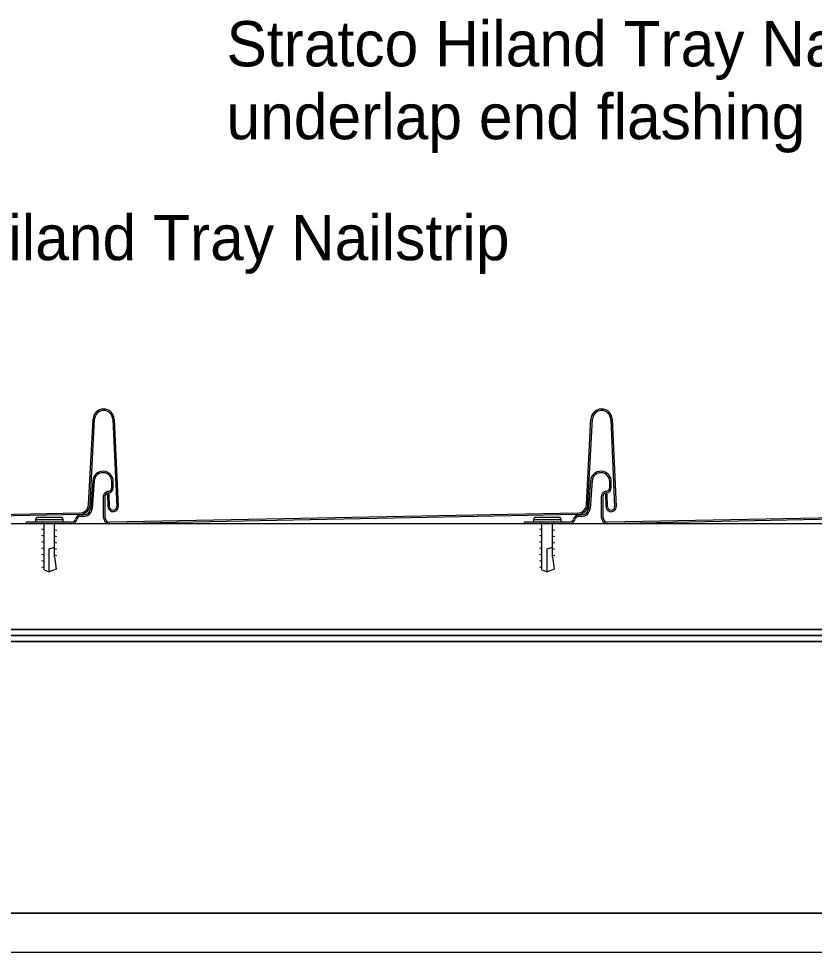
# Model space of a CAD drawing. Extents: x -2.36 to 6.66, y -3.72 to 4.13.
# Drawn here: x 4.3584 to 4.622, y -3.277 to -2.9677 of the extents above; entities that cross this region are included whole.
import ezdxf

# ---------------------------------------------------------------- set-up
doc = ezdxf.new("R2010")
doc.units = 0
for name, color, linetype in [('A-____-____-IDEN', 7, 'Continuous'), ('A-DETL-____-MEDM', 7, 'Continuous'), ('A-DETL-GENF-OTLN', 7, 'Continuous'), ('A-WALL-____-MCUT', 7, 'Continuous'), ('A-WALL-____-PATT', 7, 'Continuous'), ('A-WALL-FNSH-MCUT', 7, 'Continuous')]:
    doc.layers.add(name, color=color, linetype=linetype)

# ---------------------------------------------------------------- blocks, each defined once
blk = doc.blocks.new('Detail Repeating_Stratco_Hiland_Tray_Nailstrip - Rib Height 38mm_165mm Coverage-Detail Flashings - Hiland Nailstrip End Caps')
at = {"layer": 'A-DETL-____-MEDM'}
for p, q in [((0.17571069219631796, 7.14861503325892e-16), (0.1905651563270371, 7.14861503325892e-16)), ((0.1905651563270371, 7.14861503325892e-16), (0.1905651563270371, -0.0004999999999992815)), ((0.3407106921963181, 1.4974022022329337e-15), (0.35556515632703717, 1.4974022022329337e-15)), ((0.35556515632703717, 1.4974022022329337e-15), (0.35556515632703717, -0.0004999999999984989)), ((0.008000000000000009, -0.0035284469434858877), (0.16297544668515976, -0.0005002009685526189)), ((0.00800101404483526, -0.0030284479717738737), (0.16296726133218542, -2.6797304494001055e-07)), ((0.1644999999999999, -0.002), (0.1644999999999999, -0.009238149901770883)), ((0.1649999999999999, -0.002), (0.1649999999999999, -0.009238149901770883)), ((0.17162103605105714, -0.002413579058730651), (0.17257033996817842, -0.002413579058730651)), ((0.17162103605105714, -0.002913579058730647), (0.17257033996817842, -0.002913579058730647)), ((0.1730000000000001, -0.0035284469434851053), (0.3279754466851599, -0.0005002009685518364)), ((0.1730010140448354, -0.0030284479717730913), (0.3279672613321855, -2.679730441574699e-07)), ((0.17571069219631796, -0.0004999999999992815), (0.1905651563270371, -0.0004999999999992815)), ((0.32950000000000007, -0.0019999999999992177), (0.32950000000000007, -0.0092381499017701)), ((0.32999999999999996, -0.0019999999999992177), (0.32999999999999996, -0.0092381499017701)), ((0.33662103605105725, -0.002413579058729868), (0.3375703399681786, -0.002413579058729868)), ((0.33662103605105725, -0.0029135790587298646), (0.3375703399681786, -0.0029135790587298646)), ((0.3379999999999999, -0.003528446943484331), (0.4929754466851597, -0.0005002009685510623)), ((0.3380010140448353, -0.0030284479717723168), (0.4929672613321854, -2.679730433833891e-07)), ((0.3407106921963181, -0.0004999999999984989), (0.35556515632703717, -0.0004999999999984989)), ((0.16148096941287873, -0.03458502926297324), (0.16017240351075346, -0.005699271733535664)), ((0.16198063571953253, -0.03456634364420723), (0.16067207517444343, -0.00568070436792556)), ((0.1630061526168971, -0.005613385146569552), (0.16313200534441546, -0.009787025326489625)), ((0.16350592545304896, -0.005598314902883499), (0.16363177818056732, -0.009771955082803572)), ((0.16813551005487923, -0.014184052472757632), (0.16879587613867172, -0.00504202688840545)), ((0.1686342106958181, -0.014220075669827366), (0.16929457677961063, -0.005078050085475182)), ((0.32648096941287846, -0.03458502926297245), (0.32517240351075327, -0.005699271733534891)), ((0.32698063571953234, -0.034566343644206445), (0.32567207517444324, -0.005680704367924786)), ((0.3280061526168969, -0.005613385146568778), (0.3281320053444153, -0.009787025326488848)), ((0.3285059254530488, -0.005598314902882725), (0.32863177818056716, -0.009771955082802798)), ((0.33313551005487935, -0.014184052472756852), (0.3337958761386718, -0.005042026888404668)), ((0.3336342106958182, -0.014220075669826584), (0.3342945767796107, -0.005078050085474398)), ((0.16949871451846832, -0.006345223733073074), (0.1680156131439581, -0.03463810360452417)), ((0.16999802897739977, -0.006371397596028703), (0.16851492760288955, -0.034664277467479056)), ((0.3344987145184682, -0.0063452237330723), (0.33301561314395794, -0.0346381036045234)), ((0.3349980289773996, -0.00637139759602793), (0.3335149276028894, -0.03466427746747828)), ((0.16179429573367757, -0.012056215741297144), (0.16179429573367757, -0.013973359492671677)), ((0.16229429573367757, -0.012056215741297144), (0.16229429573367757, -0.013973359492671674)), ((0.16363177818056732, -0.009771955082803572), (0.16313200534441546, -0.009787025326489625)), ((0.3267942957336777, -0.012056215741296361), (0.3267942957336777, -0.013973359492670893)), ((0.3272942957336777, -0.012056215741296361), (0.3272942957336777, -0.013973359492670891)), ((0.32863177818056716, -0.009771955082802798), (0.3281320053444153, -0.009787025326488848))]:
    blk.add_line(p, q, dxfattribs=at)
for centre, radius, start, end in [((0.1629999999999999, -0.002), 0.0020000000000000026, 359.9999999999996, 90.00000000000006), ((0.17571069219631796, -0.0019038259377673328), 0.0019038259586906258, 90, 165.0895671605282), ((0.32799999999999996, -0.0019999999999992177), 0.0020000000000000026, 359.9999999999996, 90.00000000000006), ((0.3407106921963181, -0.00190382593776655), 0.0019038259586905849, 90, 165.08956716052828), ((0.1629999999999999, -0.002), 0.0015000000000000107, 359.99999999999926, 89.99999999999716), ((0.17162103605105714, -0.005246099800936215), 0.002832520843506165, 90, 175.86846616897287), ((0.17162103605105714, -0.005246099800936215), 0.0023325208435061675, 90, 175.8684661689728), ((0.1729939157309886, -0.006528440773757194), 0.0035000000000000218, 89.88379894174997, 176.99932472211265), ((0.17257033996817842, -0.0010676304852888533), 0.0013459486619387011, 269.9999999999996, 345.0895671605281), ((0.17257033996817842, -0.0010676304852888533), 0.0018459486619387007, 269.9999999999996, 345.08956716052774), ((0.17571069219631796, -0.0019038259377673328), 0.0014038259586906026, 90, 165.0895671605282), ((0.32799999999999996, -0.0019999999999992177), 0.001499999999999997, 1.3994440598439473e-13, 89.99999999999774), ((0.33662103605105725, -0.005246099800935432), 0.002832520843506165, 90, 175.86846616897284), ((0.33662103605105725, -0.005246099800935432), 0.002332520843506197, 90, 175.86846616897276), ((0.33799391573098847, -0.006528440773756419), 0.0034999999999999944, 89.88379894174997, 176.99932472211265), ((0.3375703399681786, -0.0010676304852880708), 0.0013459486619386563, 269.9999999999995, 345.08956716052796), ((0.3375703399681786, -0.0010676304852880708), 0.0018459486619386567, 269.99999999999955, 345.0895671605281), ((0.3407106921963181, -0.00190382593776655), 0.0014038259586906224, 90, 165.08956716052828), ((0.16183853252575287, -0.005648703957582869), 0.001666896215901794, 91.69561024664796, 181.73841940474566), ((0.16183853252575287, -0.005648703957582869), 0.0011668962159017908, 91.68553350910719, 181.57144938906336), ((0.16183989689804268, -0.005648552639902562), 0.0016667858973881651, 1.727184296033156, 91.74264393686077), ((0.16183989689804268, -0.005648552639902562), 0.0011667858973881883, 1.7271842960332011, 91.75272148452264), ((0.1729939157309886, -0.006528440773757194), 0.0029999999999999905, 89.88379894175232, 173.99932472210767), ((0.3268385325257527, -0.005648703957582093), 0.0016668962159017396, 91.69561024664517, 181.73841940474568), ((0.3268385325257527, -0.005648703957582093), 0.0011668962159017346, 91.6855335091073, 181.5714493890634), ((0.3268398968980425, -0.005648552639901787), 0.001666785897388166, 1.7271842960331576, 91.74264393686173), ((0.3268398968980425, -0.005648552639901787), 0.0011667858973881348, 1.7271842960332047, 91.75272148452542), ((0.33799391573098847, -0.006528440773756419), 0.002999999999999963, 89.88379894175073, 173.9993247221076), ((0.1635613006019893, -0.009238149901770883), 0.0009386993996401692, 263.63492002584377, 0), ((0.1635613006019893, -0.009238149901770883), 0.001438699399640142, 266.42375988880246, 0), ((0.3285613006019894, -0.0092381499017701), 0.0009386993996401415, 263.63492002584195, 0), ((0.3285613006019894, -0.0092381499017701), 0.001438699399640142, 266.4237598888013, 0), ((0.16369429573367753, -0.012056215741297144), 0.0019000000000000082, 97.16745519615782, 180), ((0.16369429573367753, -0.012056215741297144), 0.0014000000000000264, 99.1545104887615, 180), ((0.3286942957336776, -0.012056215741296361), 0.0019000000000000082, 97.16745519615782, 180), ((0.3286942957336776, -0.012056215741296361), 0.0013999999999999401, 99.15451048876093, 180), ((0.1652187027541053, -0.013973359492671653), 0.0034244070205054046, 180.0000000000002, 355.8684661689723), ((0.1652187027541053, -0.013973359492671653), 0.0029244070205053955, 180.0000000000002, 355.8684661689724), ((0.3302187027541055, -0.01397335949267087), 0.003424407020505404, 180.00000000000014, 355.8684661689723), ((0.3302187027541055, -0.01397335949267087), 0.002924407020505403, 180.0000000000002, 355.8684661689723), ((0.16499966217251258, -0.03447919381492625), 0.0035202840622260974, 181.72282641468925, 271.72822929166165), ((0.16499966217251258, -0.03447919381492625), 0.0030202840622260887, 181.65349035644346, 271.72910695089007), ((0.16500033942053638, -0.03448004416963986), 0.00301941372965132, 271.71674837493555, 356.9993247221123), ((0.16500033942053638, -0.03448004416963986), 0.0035194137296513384, 271.7176262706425, 356.9993247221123), ((0.3299996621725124, -0.03447919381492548), 0.0035202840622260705, 181.72282641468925, 271.7282292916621), ((0.3299996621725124, -0.03447919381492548), 0.0030202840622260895, 181.65349035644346, 271.7291069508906), ((0.33000033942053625, -0.03448004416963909), 0.0030194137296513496, 271.7167483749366, 356.9993247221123), ((0.33000033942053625, -0.03448004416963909), 0.0035194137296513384, 271.71762627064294, 356.9993247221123)]:
    blk.add_arc(centre, radius, start, end, dxfattribs=at)
at = {"layer": 'A-DETL-GENF-OTLN'}
for p, q in [((0.18067801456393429, 0.015091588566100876), (0.1829999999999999, 0.015936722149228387)), ((0.18299999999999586, 0.015936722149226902), (0.18299999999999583, 0.008320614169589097)), ((0.18474999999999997, 0.015299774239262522), (0.1829999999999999, 0.015936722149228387)), ((0.3456780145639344, 0.015091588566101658), (0.34800000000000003, 0.015936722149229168)), ((0.3479999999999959, 0.015936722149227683), (0.3479999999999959, 0.008320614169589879)), ((0.34975000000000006, 0.015299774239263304), (0.34800000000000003, 0.015936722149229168)), ((0.18124999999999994, 0.011021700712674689), (0.18067801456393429, 0.015091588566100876)), ((0.18474999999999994, 0.015299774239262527), (0.1847499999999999, 0.000223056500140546)), ((0.18474999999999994, 0.014598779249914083), (0.18549999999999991, 0.014360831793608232)), ((0.18474999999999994, 0.012500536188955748), (0.18549999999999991, 0.012262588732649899)), ((0.34625000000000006, 0.011021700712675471), (0.3456780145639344, 0.015091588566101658)), ((0.34975000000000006, 0.015299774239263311), (0.34975, 0.00022305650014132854)), ((0.34975000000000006, 0.014598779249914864), (0.35050000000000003, 0.014360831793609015)), ((0.34975, 0.01250053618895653), (0.3505, 0.012262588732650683)), ((0.18049999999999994, 0.01067627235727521), (0.18124999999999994, 0.010438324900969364)), ((0.18124999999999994, 0.011021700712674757), (0.1812499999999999, 0.00022305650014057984)), ((0.18474999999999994, 0.010402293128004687), (0.18549999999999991, 0.010164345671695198)), ((0.34550000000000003, 0.010676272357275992), (0.34625, 0.010438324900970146)), ((0.34625, 0.01102170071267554), (0.34625, 0.0002230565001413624)), ((0.34975, 0.010402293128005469), (0.3505, 0.010164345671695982)), ((0.18049999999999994, 0.008578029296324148), (0.18124999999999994, 0.008340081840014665)), ((0.18049999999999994, 0.006479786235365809), (0.18124999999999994, 0.006241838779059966)), ((0.18299999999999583, 0.008320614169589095), (0.18124999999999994, 0.00781847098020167)), ((0.18474999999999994, 0.00830405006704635), (0.18549999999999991, 0.0080661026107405)), ((0.18474999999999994, 0.006205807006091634), (0.18549999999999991, 0.005967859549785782)), ((0.34550000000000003, 0.00857802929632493), (0.34625, 0.008340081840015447)), ((0.34550000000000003, 0.006479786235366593), (0.34625, 0.0062418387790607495)), ((0.3479999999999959, 0.008320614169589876), (0.34625000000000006, 0.007818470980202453)), ((0.34975, 0.008304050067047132), (0.3505, 0.008066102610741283)), ((0.34975, 0.006205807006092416), (0.3505, 0.005967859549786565)), ((0.18049999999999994, 0.004381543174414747), (0.18124999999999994, 0.004143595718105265)), ((0.18474999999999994, 0.004107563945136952), (0.18549999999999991, 0.0038696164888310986)), ((0.34550000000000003, 0.004381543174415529), (0.34625, 0.004143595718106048)), ((0.34975, 0.004107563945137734), (0.3505, 0.0038696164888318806)), ((0.1804999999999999, 0.002283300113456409), (0.1812499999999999, 0.002045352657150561)), ((0.1847499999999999, 0.00200932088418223), (0.1854999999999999, 0.0017713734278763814)), ((0.34550000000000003, 0.0022833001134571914), (0.34625, 0.0020453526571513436)), ((0.34975, 0.0020093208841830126), (0.3505, 0.001771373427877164)), ((0.17899470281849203, -0.0022175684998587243), (0.17844206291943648, -0.001277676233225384)), ((0.17844780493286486, -0.0012874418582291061), (0.18755219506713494, -0.0012874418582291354)), ((0.1870999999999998, -0.0005769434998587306), (0.1789, -0.0005769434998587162)), ((0.1870052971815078, -0.0022175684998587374), (0.17899470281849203, -0.002217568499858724)), ((0.18755219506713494, -0.001287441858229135), (0.1870052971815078, -0.002217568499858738)), ((0.3439947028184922, -0.002217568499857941), (0.3434420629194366, -0.0012776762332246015)), ((0.3434478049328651, -0.0012874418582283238), (0.3525521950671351, -0.001287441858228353)), ((0.3520999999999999, -0.0005769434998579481), (0.34390000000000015, -0.0005769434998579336)), ((0.35200529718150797, -0.0022175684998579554), (0.34399470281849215, -0.002217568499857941)), ((0.3525521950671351, -0.0012874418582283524), (0.35200529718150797, -0.0022175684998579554))]:
    blk.add_line(p, q, dxfattribs=at)
for centre, radius, start, end in [((0.18045000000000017, 0.00022305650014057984), 0.0007999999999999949, 269.99999999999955, 359.99999999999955), ((0.18554999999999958, 0.000223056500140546), 0.0007999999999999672, 179.99999999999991, 269.9999999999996), ((0.34545000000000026, 0.0002230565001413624), 0.0007999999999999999, 269.99999999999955, 359.9999999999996), ((0.35054999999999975, 0.00022305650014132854), 0.0007999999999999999, 179.99999999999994, 269.9999999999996), ((0.1789, -0.0010769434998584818), 0.0005000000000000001, 90.00000000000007, 203.66982389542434), ((0.18709999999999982, -0.0010769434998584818), 0.0004999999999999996, 336.3301761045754, 89.99999999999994), ((0.34390000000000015, -0.0010769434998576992), 0.000500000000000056, 90.00000000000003, 203.6698238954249), ((0.3520999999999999, -0.0010769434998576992), 0.0004999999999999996, 336.3301761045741, 90)]:
    blk.add_arc(centre, radius, start, end, dxfattribs=at)

msp = doc.modelspace()

# ---------------------------------------------------------------- linework, layer by layer
at = {"layer": 'A-WALL-____-MCUT'}
for p, q in [((4.681520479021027, -3.1350250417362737), (4.063712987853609, -3.135025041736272)), ((4.681520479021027, -3.1700250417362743), (4.063712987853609, -3.170025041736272)), ((4.7815204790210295, -3.172025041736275), (3.9937129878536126, -3.172025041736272)), ((4.736520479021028, -3.174025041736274), (4.038712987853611, -3.1740250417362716)), ((4.736520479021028, -3.264025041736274), (4.038712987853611, -3.264025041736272))]:
    msp.add_line(p, q, dxfattribs=at)
at = {"layer": 'A-WALL-____-PATT'}
for p, q in [((4.681520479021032, -3.135025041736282), (4.063712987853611, -3.1350250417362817)), ((4.7815204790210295, -3.1700250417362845), (3.9937129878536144, -3.1700250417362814)), ((4.063712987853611, -3.1700250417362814), (4.681520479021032, -3.1700250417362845)), ((3.9937129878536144, -3.1720250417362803), (4.75152047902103, -3.172025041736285)), ((4.7815204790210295, -3.172025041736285), (3.9937129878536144, -3.1720250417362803)), ((4.0387129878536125, -3.1740250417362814), (4.736520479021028, -3.1740250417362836)), ((4.736520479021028, -3.1740250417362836), (4.0387129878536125, -3.1740250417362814)), ((4.7815204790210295, -3.2640250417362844), (3.9937129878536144, -3.2640250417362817)), ((4.0387129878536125, -3.2640250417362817), (4.736520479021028, -3.2640250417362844)), ((3.9937129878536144, -3.2770250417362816), (4.736520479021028, -3.277025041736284))]:
    msp.add_line(p, q, dxfattribs=at)
at = {"layer": 'A-WALL-FNSH-MCUT'}
msp.add_line((3.9937129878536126, -3.277025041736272), (4.7815204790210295, -3.277025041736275), dxfattribs=at)

# ---------------------------------------------------------------- block references
at = {"layer": 'A-DETL-GENF-OTLN', "rotation": 180}
msp.add_blockref('Detail Repeating_Stratco_Hiland_Tray_Nailstrip - Rib Height 38mm_165mm Coverage-Detail Flashings - Hiland Nailstrip End Caps', (4.716520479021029, -3.135025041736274), dxfattribs=at)

# ---------------------------------------------------------------- texts
at = {"layer": 'A-____-____-IDEN'}
for s, p in [('Stratco Hiland Tray Nailstrip', (4.427225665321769, -2.9835002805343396)), ('underlap end flashing', (4.427225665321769, -3.0076435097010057)), ('Stratco Hiland Tray Nailstrip', (4.271326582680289, -3.0477176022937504))]:
    msp.add_text(s, height=0.014999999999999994, dxfattribs=at).set_placement(p)

doc.saveas('drawing.dxf')
